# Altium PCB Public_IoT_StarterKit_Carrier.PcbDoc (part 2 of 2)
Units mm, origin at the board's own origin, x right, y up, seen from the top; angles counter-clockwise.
Board outline 84.62 x 84.55 mm, 4 copper layers (Top, PWR, MID, Bottom), stack 1.612 mm thick; 85 components, 101 nets, 416 pads, 114 vias.
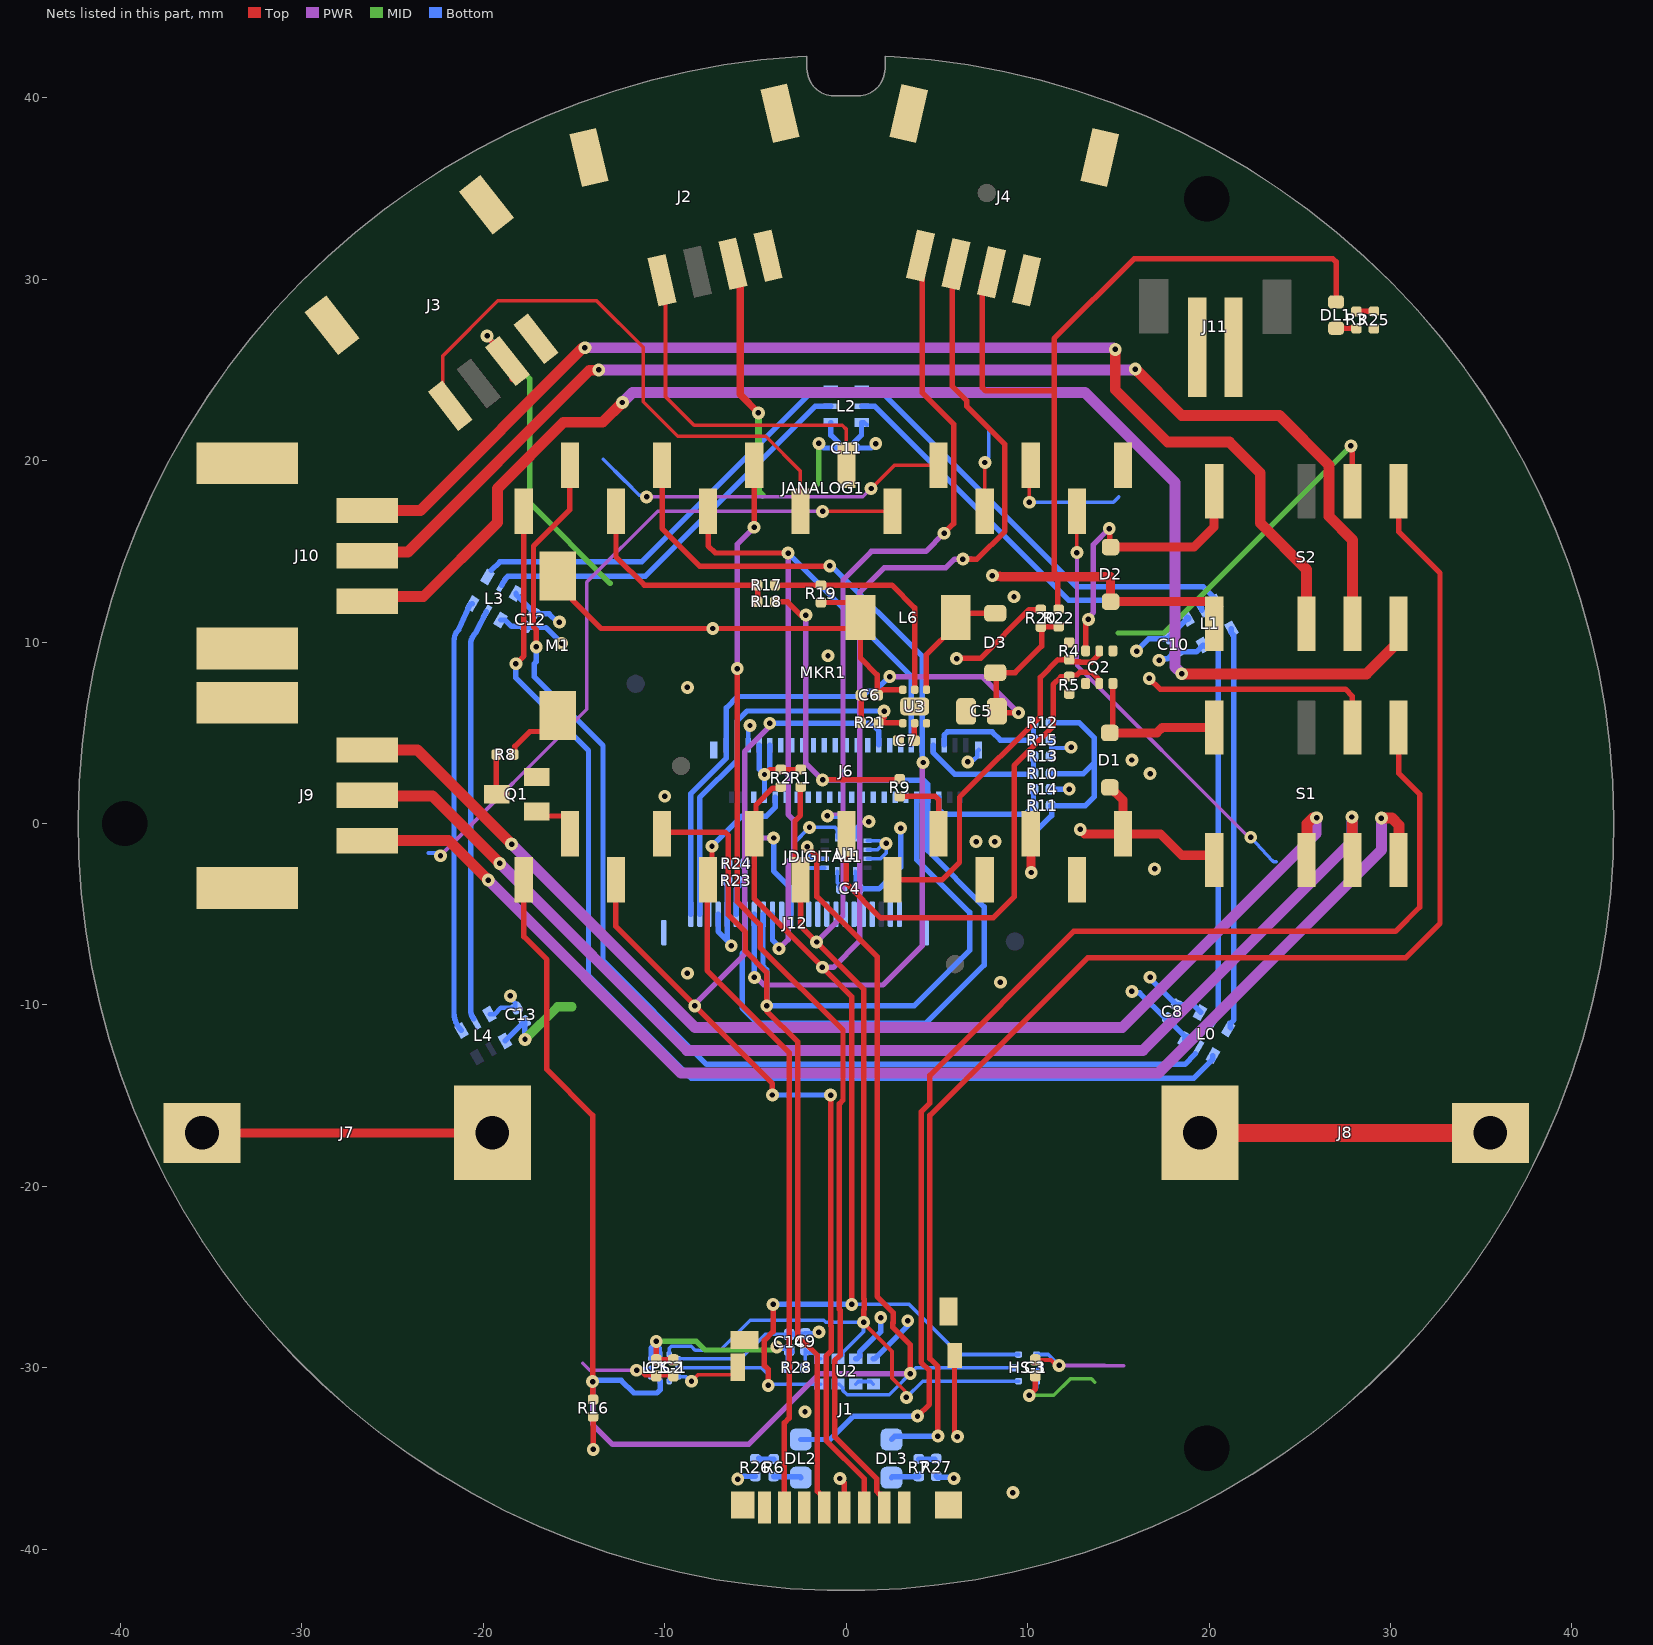
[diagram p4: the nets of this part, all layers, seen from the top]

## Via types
v1: diameter 0.706, hole 0.3, Top to Bottom, tented both sides, 114 vias

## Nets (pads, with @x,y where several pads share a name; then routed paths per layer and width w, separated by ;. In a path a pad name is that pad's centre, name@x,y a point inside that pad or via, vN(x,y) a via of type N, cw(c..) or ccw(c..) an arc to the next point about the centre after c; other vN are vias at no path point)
+5V: C8.2 C10.2 C11.2 C12.2 C13.2 D1.C D2.C DL1.A J2.3 J3.3 J4.3 JDIGITAL1.14 L0.3 L1.3 L2.3 L3.3 L4.3 MKR1.5V R22.1 S1.1 S1.9 S2.1 S2.9 | length 157.9
  Top w0.3: v1(-19.79,26.87) -19.79,26.813 -18.67,25.693 J3.3@-18.67,25.487 -18.39,25.207 J3.3@-18.39,24.475 ; J4.3@8.003,30.382 7.51,29.89 7.51,24.019 7.686,23.844 11.466,23.844 ; 8.462,13.747 8.462,13.664 8.501,13.624 8.526,13.6 ; 11.398,13.6 11.466,13.668 11.466,23.844 ; 11.66,13.6 11.66,11.922 11.745,11.837 11.752,11.837 11.752,11.822 11.727,11.797 R22.1@11.712,11.797 ; v1(16.7,8) 17.298,7.402 27.51,7.402 27.904,7.008 S1.9@27.904,5.29 ; DL1.A@27,28.743 27,30.948 26.824,31.123 15.868,31.123 11.466,26.721 11.466,23.844 ; v1(27.816,20.812) 27.904,20.724 S2.9@27.904,18.315
  Top w0.4: J2.3@-6.246,30.846 -5.842,30.442 -5.842,23.638 v1(-4.834,22.63)
  Top w0.5: v1(8.063,13.664) 8.102,13.624 8.501,13.624 ; 8.526,13.6 11.398,13.6 11.66,13.6 14.576,13.6 D2.C@14.576,12.225 20.034,12.225 S2.1@20.284,11.975 ; v1(12.9,-0.326) 13.143,-0.569 MKR1.5V@15.256,-0.569 ; D1.C@14.534,1.985 14.564,1.985 15.25,1.299 15.25,-0.563 MKR1.5V@15.256,-0.569 ; S1.1@20.284,-2.01 20.284,-2 20.034,-1.75 18.5,-1.75 17.319,-0.569 MKR1.5V@15.256,-0.569
  MID w0.3: v1(-19.79,26.87) -17.439,24.52 -17.439,17.678 -13.001,13.24 ; -1.721,18.583 -1.499,18.806 v1@-1.499,20.887 ; 15,10.5 17.504,10.5 v1(27.816,20.812)
  MID w0.4: v1(-4.834,22.63) -4.834,18.298 -4.611,18.075
  MID w0.5: v1(-17.7,-11.9) -15.9,-10.1 -15.1,-10.1 ; v1(16.7,8) v1@16.739,7.961
  Bottom w0.3: L3.3@-19.046,11.214 -18.788,11.214 -18.44,10.865 -17.65,10.865 C12.2@-17.636,10.851 -17.588,10.803 -16.551,10.803 v1(-15.685,9.938) ; L4.3@-18.796,-11.977 -17.759,-10.94 -17.703,-10.94 -17.703,-11.897 v1(-17.7,-11.9) v1@-17.776,-11.976 ; v1(-1.501,20.949) -1.247,20.694 C11.2@-0.438,20.694 ; L2.3@-0.85,22.1 -0.845,22.095 -0.845,21.4 -0.435,20.99 ; v1(16.005,9.505) 16.673,10.173 17.769,10.173 17.769,10.246 L1.3@18.824,11.301 ; v1(16.75,-8.472) 16.75,-8.555 C8.2@18.198,-10.003 18.21,-9.99 19.131,-9.99 L0.3@19.534,-10.393
  Bottom w0.4: L1.3@18.814,11.31 L1.3@18.824,11.301
BUZZER: JDIGITAL1.2 MKR1.7 Q1.1 | length 2.7
  Top w0.3: Q1.1@-17.061,0.659 -16.816,0.415 -15.574,0.415 -15.224,0.065 MKR1.7@-15.224,-0.569
CS: J6.37 J12.17 JANALOG1.11 MKR1.2 | length 50.6
  Top w0.3: MKR1.2@-10.144,19.751 -10.144,16.259 -8.056,14.171 v1@-0.929,14.171 ; v1(4.239,3.361) v1@4.239,3.471
  PWR w0.3: v1(-5.057,-8.483) -4.947,-8.483 -4.53,-8.9 2.028,-8.9 4.2,-6.728 v1@4.2,3.361
  Bottom w0.3: J12.17@-5.06,-5 -5.06,-8.48 v1(-5.057,-8.483) ; v1(-0.9,14.2) -0.8,14.2 4.2,9.2 J6.37@4.2,4.325 4.2,3.4 v1(4.239,3.361)
DB0: J6.28
DB1: J12.11
DB01: J6.27
DB2: J12.10
DB02: J6.26
DB3: J12.9
DB03: J6.25
DB4: J12.8
DB04: J6.24
DB5: J12.7
DB05: J6.23
DB6: J12.6
DB06: J6.22
DB7: J12.5
DB07: J6.21
DB08: J6.20
DB09: J6.19
DB10: J6.18
DB11: J6.17
DB12: J6.16
DB13: J6.15
DB14: J6.14
DB15: J6.13
DB16: J6.12
DB17: J6.11
DE: J6.31
DIN(SDA): J1.3 J6.29 J12.13 JDIGITAL1. MKR1.8 | length 72.8
  Top w0.3: MKR1.8@-12.684,-3.109 -12.7,-3.124 -12.7,-5.66 -8.342,-10.018 v1(-8.342,-10.054) -4.062,-14.333 v1(-4.062,-14.962) ; v1(-0.855,-14.97) -0.855,-27.676 -0.814,-27.718 -0.814,-29.057 -1.108,-29.352 -1.108,-33.991 0.998,-36.097 J1.3@0.998,-37.694
  PWR w0.3: v1(-8.342,-10.054) -8.342,-9.955 -5.6,-7.213 -5.6,-0.863 ; v1(-4.211,5.52) -4.211,5.357 -5.6,3.968 -5.6,-0.863 ; v1(-4,-0.8) -5.537,-0.8 -5.6,-0.863
  Bottom w0.3: v1(-4.211,5.52) 1.367,5.52 1.8,5.087 J6.29@1.8,4.325 ; v1(-4.062,-14.962) -0.863,-14.962 v1(-0.855,-14.97) ; v1(-4,-0.8) -4,-2.607 -3.06,-3.547 J12.13@-3.06,-5
DISP_BL: R17.2 R19.1 U3.5 | length 12.7
  Top w0.3: R17.2@-3.924,13.132 -3.923,13.131 -1.387,13.131 R19.1@-1.386,13.13 -1.384,13.132 2.526,13.132 3.775,11.883 U3.5@3.775,7.373
DISP_DC: J6.35 J12.15 JANALOG1.10 MKR1.1 | length 44.2
  Top w0.3: MKR1.1@-7.604,17.211 -7.604,15.304 -7.207,14.907 -3.507,14.907 -3.5,14.9 v1(-3.2,14.9)
  PWR w0.3: v1(-3.7,-6.9) -3.2,-6.4 -3.2,-2.107 -2.9,-1.807 -2.9,0.2 -3.2,0.5 v1(-3.2,14.9)
  Bottom w0.3: J12.15@-4.06,-5 -4.06,-6.43 -3.7,-6.79 v1(-3.7,-6.9) ; v1(-3.2,14.9) 3.6,8.1 J6.35@3.6,4.325
DISP_RST: J6.38 J12.18 R9.1 R18.2 | length 53.1
  Top w0.3: R18.2@-3.924,12.215 -3.229,12.215 -2.503,11.489 v1(-2.219,11.489) ; v1(-1.3,2.4) 2.9,2.4 R9.1@2.95,2.45
  PWR w0.3: v1(-2.219,11.489) -2.219,3.319 v1(-1.3,2.4)
  Bottom w0.3: J12.18@-5.56,-5 -5.56,-6.998 -5.738,-7.177 -5.738,-10.162 -4.9,-11 4.4,-11 7.6,-7.8 7.6,-4.6 4.5,-1.5 J6.38@4.5,1.45 4.5,2.158 4.267,2.391 -1.291,2.391 v1(-1.3,2.4)
GND: C1.2 C2.1 C3.1 C4.1 C5.1 C6.1 C7.1 C8.1 C9.1 C10.1 C11.1 C12.1 C13.1 C14.2 HS-1.5 J1.6 J1.CD2 J1.SH1 J1.SH2 J1.SH3 J1.SH4 J2.4 J2.SS1 J2.SS2 J3.4 J3.SS1 J3.SS2 J4.4 J4.SS1 J4.SS2 J6.5 J6.6 J6.MP1 J6.MP2 J7.1 J7.2 J7.- J9.MP1 J9.MP2 J10.MP1 J10.MP2 J11.1 J12.1 J12.2 J12.14 J12.22 J12.MP1 J12.MP2 JDIGITAL1.11 L0.4 L1.4 L2.4 L3.4 L4.4 LPS-1.3 LPS-1.5 LPS-1.8 LPS-1.9 MKR1.GND pad.H10 pad.H11 Q1.2 Q2.1 Q2.4 R4.2 R5.2 R13.1 R14.1 R15.1 R21.1 R24.1 R25.1 R26.1 R27.1 U1.1 U1.2 U1.3 U1.6 U1.7 U2.6 U3.3 U3.7 | length 81.3
  Top w0.2: v1(-11.548,-30.127) -11.411,-30.127 -11.104,-30.435 C1.2@-10.465,-30.435 C2.1@-9.519,-30.435 ; v1(-8.524,-30.742) -8.152,-30.37 -6.277,-30.37 -5.977,-30.07 J1.SH4@-5.977,-29.969 ; J1.CD2@-5.977,-28.842 J1.CD2@-5.604,-28.469 ; C3.1@10.425,-29.565 11.293,-29.565 11.597,-29.869 v1(11.734,-29.869)
  Top w0.3: R21.1@0.831,5.55 0.834,5.553 0.834,7.07 C6.1@0.838,7.073 ; J1.SH3@5.973,-29.319 5.973,-33.524 6.131,-33.682 v1(6.131,-33.792) ; MKR1.GND@7.636,-3.109 7.553,-3.025 MKR1.GND@7.7,-2.878
  Top w0.5: J7.1@-35.5,-17.049 J7.-@-19.5,-17.049 J7.2@-18.543,-16.092
  PWR w0.2: -14.51,-29.75 -14.133,-30.127 v1(-11.548,-30.127) ; v1(11.734,-29.869) 14.258,-29.869 14.249,-29.878 15.302,-29.878
  Bottom w0.2: v1(-11.548,-30.127) -11.461,-30.04 -10.785,-30.04 LPS-1.9@-10.745,-30 LPS-1.8@-10.745,-30.5 ; LPS-1.3@-9.255,-29.5 -5.802,-29.5 -4.458,-28.156 -3.22,-28.156 C14.2@-3.162,-28.214 ; LPS-1.5@-9.228,-30.527 LPS-1.5@-9.255,-30.5 -8.821,-30.5 -8.58,-30.742 v1(-8.524,-30.742) ; U1.7@-0.5,-2.625 -0.5,-3.232 -0.235,-3.498 0,-3.263 U1.6@0,-2.625 ; U1.3@1.175,-1.95 1.891,-1.95 2.2,-1.641 v1(2.2,-1.1) ; U1.2@1.175,-1.45 1.726,-1.45 v1@2,-1.176 ; U1.1@1.175,-0.95 1.85,-0.95 v1@2,-1.1 ; HS-1.5@10.49,-29.265 HS-1.5@10.5,-29.265 11.131,-29.265 v1(11.734,-29.869) ; R13.1@11.275,3.695 11.275,4.135 ; R15.1@11.275,4.6 11.275,4.135 ; v1(12.4,4.2) 12.36,4.16 11.3,4.16 11.275,4.135
  Bottom w0.25: L4.4@-19.646,-10.505 -19.374,-10.505 -19.028,-10.159 -18.287,-10.159 -18.226,-10.098 -18.226,-9.897 -18.5,-9.624 v1(-18.5,-9.5) v1@-18.641,-9.5 ; J6.5@-5.4,4.325 -5.4,5.3 v1(-5.3,5.4) ; C4.1@-0.374,-3.461 C4.1@-0.235,-3.6 ; L2.4@0.85,22.1 1,22.1 L2.4@1.125,21.975 ; v1@2,-1.176 v1@2,-1.1 ; v1(6.704,3.394) 6.791,3.481 7.011,3.481 7.225,3.696 7.225,3.975 J6.MP2@7.3,4.05
  Bottom w0.3: L3.4@-18.196,12.686 -18.196,12.62 -17.201,11.625 C12.1@-17.201,11.605 -17.153,11.557 -16.367,11.557 -15.91,11.1 v1(-15.8,11.1) ; v1(-5.977,-36.134) -5.867,-36.134 -5.709,-35.975 R26.1@-5,-35.975 ; C14.2@-3.139,-28.156 -3.126,-28.143 -2.263,-28.143 C9.1@-2.25,-28.13 -2.249,-28.131 -1.6,-28.131 v1(-1.5,-28.032) ; C11.1@0.432,20.694 1.383,20.694 v1(1.626,20.938) ; 0.435,20.99 0.845,21.4 0.845,22.095 L2.4@0.85,22.1 ; U2.6@0.53,-29.5 0.59,-29.5 0.74,-29.35 0.74,-29.136 1.68,-28.196 1.729,-28.196 1.904,-28.02 v1(1.904,-27.233) ; R27.1@4.958,-35.958 5.026,-36.026 5.874,-36.026 v1(5.942,-36.095) ; R14.1@11.275,1.9 v1(12.3,1.9) ; v1(15.75,-9.25) 15.828,-9.328 16.179,-9.328 17.607,-10.756 C8.1@17.763,-10.756 17.763,-10.827 L0.4@18.742,-11.807 ; v1(17.25,9) 17.328,9.078 17.707,9.078 18.096,9.467 C10.1@18.252,9.467 18.264,9.455 19.299,9.455 L1.4@19.674,9.829 L1.4@19.749,9.754 ; L0.4@18.651,-11.897 L0.4@18.742,-11.807 ; L0.4@18.742,-11.807 18.796,-11.753 18.796,-11.86 L0.4@18.742,-11.807
  other v1: 9.193,-36.871 -2.267,-32.421 8.5,-8.75 -8.75,-8.25 17,-2.5 7.159,-1 8.2,-1 -10,1.5 16.75,2.75 15.75,3.5 -8.75,7.5 -1,9.25 9.25,12.5
GROVE_AN5: J2.1 JANALOG1.7 MKR1.A5 | length 19.2
  Top w0.2: J2.1@-10.143,29.946 -9.952,29.755 -9.952,23.521 -8.38,21.949 -0.219,21.949 0.016,21.714 MKR1.A5@0.016,19.751
GROVE_AN6: J3.1 JANALOG1.8 MKR1.A6 | length 31.9
  Top w0.2: J3.1@-21.752,22.918 -22.239,23.405 -22.239,25.767 -19.197,28.808 -13.756,28.808 -11.188,26.24 -11.188,23.25 -9.277,21.339 -4.438,21.339 -2.524,19.425 MKR1.A6@-2.524,17.211
HSYNC: J6.32
IM0: J6.39 R10.1 R13.2 | length 7.4
  Bottom w0.3: J6.39@4.8,4.325 4.8,3.9 5.987,2.713 10.289,2.713 R10.1@10.325,2.749 R13.2@10.325,3.695
IM1: J6.40 R11.1 R14.2 | length 7.1
  Bottom w0.3: J6.40@5.1,1.45 5.1,0.8 5.4,0.5 9.852,0.5 10.185,0.833 10.2,0.833 10.325,0.958 R11.1@10.325,0.973 R14.2@10.325,1.9
IM2: J6.41 R12.1 R15.2 | length 6.7
  Bottom w0.3: J6.41@5.4,4.325 5.4,4.877 5.576,5.053 8.043,5.053 8.496,4.6 R15.2@10.325,4.6 R12.1@10.325,5.547
INT: HS-1.3 JDIGITAL1.1 LPS-1.7 MKR1.6 R16.1 U1.9 U2.2 | length 100.3
  Top w0.3: MKR1.6@-17.764,-3.109 -17.764,-6.236 -16.5,-7.5 -16.5,-13.552 -13.973,-16.079 v1(-13.973,-30.758) ; v1@-13.961,-30.719 -13.961,-31.731 R16.1@-13.949,-31.743 ; v1(-2.139,-1.293) -2.126,-1.293 -1.609,-1.81 -1.609,-4.031 1.702,-7.342 1.702,-26.068 2.585,-26.951 2.585,-27.516 2.575,-27.526 2.575,-27.775 3.535,-28.735 v1(3.535,-30.316)
  PWR w0.3: v1(-13.973,-30.758) -13.973,-33.113 -12.874,-34.212 -12.281,-34.212 -12.274,-34.205 -5.357,-34.205 -1.468,-30.316 v1(3.535,-30.316)
  Bottom w0.2: v1(-2.139,-1.293) -2.042,-1.39 -2.042,-1.809 -1.902,-1.95 U1.9@-1.175,-1.95 ; U2.2@-0.44,-30.9 -0.38,-30.9 -0.18,-31.1 -0.18,-31.243 0.055,-31.478 2.373,-31.478 3.851,-30 HS-1.3@9.265,-30
  Bottom w0.3: v1(-13.973,-30.758) -13.904,-30.69 -12.399,-30.69 -11.704,-31.386 -10.426,-31.386 -10.25,-31.21 LPS-1.7@-10.25,-30.745
LEDA: C5.2 D3.C J6.1 J12.24 R20.1 R22.2 | length 39
  Top w0.3: C5.2@7.998,6.1 C5.2@8.23,6.1 ; C5.2@8.122,5.992 C5.2@8.23,6.1 ; v1(9.5,6.1) C5.2@8.23,6.1 ; R22.2@11.712,10.847 11.706,10.841 10.736,10.841 R20.1@10.73,10.834 10.768,10.796 10.768,9.779 9.308,8.32 D3.C@8.219,8.32 8.263,8.275 8.263,6.222 C5.2@8.308,6.178 C5.2@8.23,6.1
  PWR w0.3: v1(2.4,8.1) 7.5,8.1 v1(9.5,6.1)
  Bottom w0.3: J12.24@-8.56,-5 -8.56,1.64 -6.6,3.6 J6.1@-6.6,4.325 -6.6,6.375 -5.975,7 0.9,7 1.2,7.3 1.6,7.3 v1(2.4,8.1)
LEDCKI: JANALOG1.13 L0.5 MKR1.4 | length 65.1
  Top w0.3: v1(-17.083,9.735) -17.083,10.683 -17.23,10.83 -17.23,15.292 -15.224,17.298 MKR1.4@-15.224,19.751
  Bottom w0.3: v1(-17.083,9.735) -17.083,8.921 -17.2,8.804 -17.2,8.1 -13.4,4.3 -13.4,-7.556 -7.687,-13.269 18.662,-13.269 L0.5@19.235,-12.696
LEDK: J6.3 J12.23 R21.2 U3.1 | length 22
  Top w0.3: v1(2.094,6.196) 2.094,5.863 R21.2@1.781,5.55 3.098,5.55 U3.1@3.125,5.523
  Bottom w0.3: J12.23@-8.06,-5 -8.073,-4.987 -8.073,1.427 -6,3.5 J6.3@-6,4.325 -6,5.663 -5.462,6.201 2.089,6.201 v1(2.094,6.196)
LEDSDI: JANALOG1.14 L0.6 MKR1.5 | length 64.8
  Top w0.3: v1(-18.2,8.8) -17.764,9.236 MKR1.5@-17.764,17.211
  Bottom w0.3: v1(-18.2,8.8) -18.2,8.022 -14.2,4.022 -14.2,-8.385 -8.536,-14.048 19.147,-14.048 20.21,-12.986 L0.6@20.21,-12.797
MISO: J1.7 J6.10 JDIGITAL1.5 MKR1.10 | length 43.5
  Top w0.3: v1(-7.392,-1.249) -7.392,-2.896 -7.662,-3.166 -7.662,-8.101 -3.139,-12.624 -3.139,-32.765 -3.402,-33.028 J1.7@-3.402,-37.694
  Bottom w0.3: v1(-7.392,-1.249) -5.744,0.4 -4.4,0.4 -3.9,0.9 J6.10@-3.9,1.45
NetC7_2: C7.2 U3.2 | length 1
  Top w0.3: C7.2@3.754,4.57 3.765,4.58 3.765,5.512 U3.2@3.775,5.523
NetC9_2: C9.2 R28.1 U2.8 | length 2.1
  Bottom w0.2: R28.1@-2.275,-30 -2.262,-29.988 -2.262,-29.012 C9.2@-2.25,-29 -2.066,-29.184 -1.786,-29.184 -1.47,-29.5 U2.8@-1.41,-29.5
NetD1_A: D1.A Q2.6 S1.12 | length 8.7
  Top w0.3: D1.A@14.534,4.995 14.699,5.16 Q2.6@14.699,7.715 ; S1.12@20.25,5.256 S1.12@20.284,5.29
  Top w0.5: D1.A@14.534,4.995 17.124,4.995 17.419,5.29 S1.12@20.284,5.29
NetD2_A: D2.A Q2.3 S2.12 | length 16.5
  Top w0.3: Q2.3@13.211,9.527 Q2.3@13.199,9.515 13.199,11.199 13.25,11.25 v1(13.355,11.25) ; v1(14.5,16.25) 14.538,16.212 14.538,15.273 D2.A@14.576,15.235
  Top w0.5: D2.A@14.576,15.235 19.167,15.235 20.266,16.334 20.266,18.296 S2.12@20.284,18.315
  PWR w0.3: v1(13.355,11.25) 13.355,11.358 13.626,11.629 13.626,15.376 v1(14.5,16.25)
NetD3_A: D3.A L6.2 U3.4 | length 6.8
  Top w0.3: U3.4@4.425,7.373 4.425,9.31 6.041,10.926 6.041,11.139 6.492,11.59 D3.A@8.219,11.59
NetDL1_C: DL1.C R3.2 | length 1.1
  Top w0.3: DL1.C@27,27.293 27.009,27.284 27.01,27.285 28.111,27.285 R3.2@28.118,27.278
NetDL2_A: DL2.A S1.8 | length 67.6
  Top w0.3: v1(3.931,-32.658) 4.581,-32.009 4.581,-30.135 4.138,-29.692 4.138,-15.887 4.615,-15.409 4.615,-13.877 12.543,-5.95 30.269,-5.95 31.603,-4.615 31.603,1.622 30.444,2.78 S1.8@30.444,5.29
  Bottom w0.3: DL2.A@-2.5,-33.95 -0.879,-33.95 0.413,-32.658 v1(3.931,-32.658)
NetDL2_C: DL2.C R6.2 | length 1.5
  Bottom w0.3: R6.2@-4,-35.975 -3.962,-36.013 -2.538,-36.013 DL2.C@-2.5,-36.05
NetDL3_A: DL3.A S2.8 | length 77.8
  Top w0.3: v1(5.058,-33.762) 5.058,-29.937 4.615,-29.494 4.615,-16.085 13.3,-7.4 30.829,-7.4 32.727,-5.502 32.727,13.806 30.444,16.089 S2.8@30.444,18.315
  Bottom w0.3: DL3.A@2.5,-33.95 2.687,-33.763 5.057,-33.763 v1(5.058,-33.762)
NetDL3_C: DL3.C R7.2 | length 1.5
  Bottom w0.3: DL3.C@2.5,-36.05 2.538,-36.013 3.962,-36.013 R7.2@4,-35.975
NetJ1_1: J1.1
NetJ1_8: J1.8
NetJ1_CD1: J1.CD1
NetJ9_1: J9.1 S1.3 | length 66.6
  Top w0.6: J9.1@-26.4,4.05 -23.621,4.05 v1(-18.435,-1.135) ; S1.3@25.364,-2.01 25.4,-1.974 25.4,-0.012 25.731,0.319 v1(25.93,0.319)
  PWR w0.6: v1(-18.435,-1.135) -8.321,-11.25 15.215,-11.25 25.909,-0.555 25.909,0.299 v1(25.93,0.319)
NetJ9_2: J9.2 S1.4 | length 68.6
  Top w0.6: J9.2@-26.4,1.55 -26.364,1.514 -22.798,1.514 v1(-19.086,-2.198) ; v1(27.876,0.358) 27.89,0.344 27.89,-1.996 S1.4@27.904,-2.01
  PWR w0.6: v1(-19.086,-2.198) -8.784,-12.5 16.351,-12.5 27.876,-0.974 v1(27.876,0.358)
NetJ9_3: J9.3 S1.5 | length 71.1
  Top w0.6: J9.3@-26.4,-0.95 -26.391,-0.941 -21.904,-0.941 v1(-19.728,-3.118) ; v1(29.498,0.295) 30.076,0.295 30.469,-0.098 30.469,-1.985 S1.5@30.444,-2.01
  PWR w0.6: v1(-19.728,-3.118) -9.096,-13.75 17.206,-13.75 29.498,-1.458 v1(29.498,0.295)
NetJ10_1: J10.1 S2.3 | length 66.5
  Top w0.6: J10.1@-26.4,17.25 -26.393,17.257 -23.467,17.257 -14.524,26.2 -14.418,26.2 v1(-14.398,26.221) ; v1(14.832,26.126) 14.832,23.907 17.724,21.015 21.124,21.015 22.819,19.32 22.819,16.552 25.364,14.007 S2.3@25.364,11.015
  PWR w0.6: v1(-14.398,26.221) 14.737,26.221 v1(14.832,26.126)
NetJ10_2: J10.2 S2.4 | length 68.7
  Top w0.6: J10.2@-26.4,14.75 -26.181,14.969 -24.151,14.969 -14.14,24.98 -13.656,24.98 v1(-13.636,25) ; v1(15.938,25.042) 18.498,22.482 23.873,22.482 26.61,19.745 26.61,16.933 27.91,15.633 27.91,11.021 S2.4@27.904,11.015
  PWR w0.6: v1(-13.636,25) 15.895,25 v1(15.938,25.042)
NetJ10_3: J10.3 S2.5 | length 76.8
  Top w0.6: J10.3@-26.425,12.5 -23.308,12.5 -19.224,16.584 -19.224,18.463 -15.574,22.113 -13.422,22.113 v1(-12.334,23.201) ; v1(18.5,8.25) 28.679,8.25 30.444,10.015 S2.5@30.444,11.015
  PWR w0.6: v1(-12.334,23.201) -11.775,23.761 13.166,23.761 14.875,22.052 18.127,18.8 18.127,8.623 v1(18.5,8.25)
NetJ12_19: J12.19 R23.1 R24.2 | length 3
  Bottom w0.3: J12.19@-6.06,-5 -6.06,-3.622 -5.597,-3.159 R23.1@-5.597,-3.144 -5.587,-3.134 -5.587,-2.222 R24.2@-5.577,-2.212
NetL0_2: L0.2 L1.5 | length 20.8
  Bottom w0.3: L1.5@20.453,10.279 20.499,10.233 20.499,-10.538
NetL1_2: L1.2 L2.5 | length 23.5
  Bottom w0.3: L2.5@0.85,23 1.573,23 12.273,12.3 19.179,12.3 19.603,11.876 L1.2@19.603,11.751
NetL2_2: L2.2 L3.5 | length 22.3
  Bottom w0.3: L3.5@-18.975,13.136 -18.774,13.483 -18.755,13.516 -18.639,13.632 -11.068,13.632 -4.803,19.897 -1.7,23 L2.2@-0.85,23
NetL3_2: L3.2 L4.5 | length 22.7
  Bottom w0.3: L4.5@-20.514,-10.755 cw(c-20.064,-10.306) -20.7,-10.306 -20.7,9.836 cw(c-19.761,9.836) -20.425,10.5 L3.2@-19.825,11.664
NetM1_2: M1.2 R8.2 | length 4
  Top w0.3: R8.2@-18.325,3.8 -18.253,3.872 -18.253,4.247 -17.429,5.071 -16.752,5.071 -15.902,5.921 M1.2@-15.902,5.95 ; M1.2@-16.19,5.075 M1.2@-15.902,5.363
NetQ1_3: Q1.3 R8.1 | length 2.4
  Top w0.3: Q1.3@-19.461,1.609 Q1.3@-19.261,1.609 -19.275,1.623 R8.1@-19.275,3.8
NetR3_1: R3.1 R25.2 | length 1
  Top w0.3: R3.1@28.118,28.228 28.12,28.226 29.081,28.226 R25.2@29.084,28.223
NetR6_1: R6.1 R26.2 | length 0.8
  Bottom w0.3: R26.2@-4.825,-34.97 -4.767,-34.97 -4.712,-35.025 R6.1@-4,-35.025
NetR7_1: R7.1 R27.2 | length 0.9
  Bottom w0.3: R7.1@4,-35.025 R27.2@4.88,-35.025
NetU2_3: U2.3 U2.4 | length 1.1
  Bottom w0.2: U2.3@0.53,-30.9 0.68,-30.75 1.35,-30.75 U2.4@1.5,-30.9
PA02_AIN0: JANALOG1.2 MKR1.A0 | length 24.1
  Top w0.2: MKR1.A0@12.716,17.374 MKR1.A0@12.716,17.211 12.716,14.934 v1(12.72,14.93)
  PWR w0.2: v1(12.72,14.93) 12.724,14.926 12.724,8.709 22.136,-0.703 ccw(c22.276,-0.561) 22.27,-0.761 v1(22.294,-0.762)
  Bottom w0.2: v1(22.294,-0.762) 23.479,-2.046 ccw(c23.626,-1.91) 23.626,-2.11 23.687,-2.11
PA03_VREFA: JANALOG1.1 MKR1.AREF
PA04_AIN4: JANALOG1.5 MKR1.A3 | length 20.1
  Top w0.2: v1(1.376,18.462) 2.666,19.751 MKR1.A3@5.096,19.751
  PWR w0.2: v1(-11,18.001) 0.916,18.001 v1(1.376,18.462)
  Bottom w0.2: -13.384,20.077 -12.155,18.848 -12.148,18.848 -11.398,18.098 -11.097,18.098 v1(-11,18.001)
PA05_AIN5: JANALOG1.6 MKR1.A4 | length 37.6
  Top w0.2: v1(-1.3,17.2) 2.544,17.2 MKR1.A4@2.556,17.211
  PWR w0.2: v1(-22.356,-1.772) -22.356,-1.765 -14.3,6.291 -14.3,9.34 -14.294,9.346 -14.294,13.306 -10.389,17.211 -1.311,17.211 v1(-1.3,17.2)
  Bottom w0.2: -23.021,-1.625 -22.495,-1.625 -22.356,-1.765 v1(-22.356,-1.772)
PA08_S0_I2C_SDA: HS-1.4 J4.2 JDIGITAL1.6 LPS-1.4 MKR1.11 R2.1 U1.14 U2.1 | length 109.3
  Top w0.3: v1(-4.29,-30.968) -4.29,-30.087 -4.501,-29.876 -4.501,-29.105 -4.501,-28.482 -4.023,-28.004 v1(-4.023,-26.5) ; R2.1@-3.6,2.025 -3.672,1.953 -4.047,1.953 -4.97,1.03 -4.97,-0.474 MKR1.11@-5.064,-0.569 -5.064,-4.154 -1.311,-7.907 v1(-1.311,-7.925) 0.307,-9.543 v1(0.307,-26.5) ; J4.2@6.054,30.832 5.859,30.637 5.859,24.088 6.643,23.304 6.643,22.998 8.744,20.896 8.744,16.106 7.21,14.572 v1(6.433,14.572)
  PWR w0.2: 0.738,0.044 1.191,0.044 v1(1.252,0.104)
  PWR w0.3: v1(-1.311,-7.925) -0.704,-7.925 0.738,-6.484 0.738,0.044 0.738,12.73 2.107,14.1 5.5,14.1 5.972,14.572 v1(6.433,14.572) 6.895,14.572
  Bottom w0.2: LPS-1.4@-9.255,-30 -4.678,-30 -4.292,-30.386 -4.292,-30.966 v1(-4.29,-30.968) -4.222,-30.9 U2.1@-1.41,-30.9 ; v1(0.307,-26.5) 3.464,-26.5 6.229,-29.265 HS-1.4@9.5,-29.265 ; U1.14@0.5,-0.775 0.533,-0.742 0.533,-0.251 0.888,0.104 v1(1.252,0.104)
  Bottom w0.3: v1(-4.023,-26.5) v1(0.307,-26.5)
PA09_S0_I2C_SCL: HS-1.2 J4.1 JDIGITAL1.7 LPS-1.2 MKR1.12 R1.1 U1.13 U2.7 | length 103.5
  Top w0.2: v1(0.96,-27.483) 0.96,-27.529 2.526,-29.095 2.526,-30.56 3.227,-31.262 3.227,-31.529 v1(3.324,-31.626)
  Top w0.3: MKR1.12@-2.82,-3.109 -2.82,0.149 -2.524,0.445 R1.1@-2.524,1.8 ; MKR1.12@-2.524,-3.109 -2.5,-3.133 -2.5,-5.663 v1(-1.632,-6.531) 0.96,-9.123 0.96,-26.19 0.988,-26.218 0.988,-26.782 0.96,-26.81 v1(0.96,-27.483) ; J4.1@4.105,31.282 4.189,31.198 4.189,23.752 5.924,22.017 5.924,16.524 v1(5.4,16)
  PWR w0.2: v1(-1.032,0.421) -0.949,0.504 -0.174,0.504
  PWR w0.3: v1(-1.632,-6.531) -0.174,-5.074 -0.174,0.504 -0.174,13.433 1.393,15 4.4,15 v1(5.4,16)
  Bottom w0.2: LPS-1.2@-9.75,-29.255 -9.75,-28.934 -9.633,-28.817 -8.537,-28.817 -8.324,-29.03 -6.94,-29.03 -5.279,-27.369 -1.233,-27.369 -1.119,-27.483 v1(0.96,-27.483) 0.96,-28.017 -0.18,-29.157 -0.18,-29.3 -0.38,-29.5 U2.7@-0.44,-29.5 ; v1(-1.032,0.421) -0.955,0.344 -0.174,0.344 0,0.17 U1.13@0,-0.775 ; v1(3.324,-31.626) 4.215,-30.735 HS-1.2@9.5,-30.735
PA11_TCC0-W3: JANALOG1.12 MKR1.3 R17.1 R18.1 | length 11.9
  Top w0.3: MKR1.3@-12.684,17.211 -12.684,14.7 -11.116,13.132 R17.1@-4.874,13.132 R18.1@-4.874,12.215
PA17_S1_SCK: J1.5 J6.36 J12.16 JDIGITAL1.4 MKR1.9 | length 70.9
  Top w0.3: MKR1.9@-10.144,-1.181 MKR1.9@-10.144,-0.569 -10.046,-0.47 -6.676,-0.47 -6.5,-0.646 -6.5,-5.028 -5.56,-5.968 -5.56,-7.017 -4.376,-8.201 -4.376,-10.04 v1(-4.378,-10.042) -4.378,-10.32 -2.662,-12.036 -2.662,-28.293 -2.242,-28.713 -2.179,-28.713 -1.586,-29.305 -1.586,-36.793 -1.41,-36.969 -1.402,-36.969 -1.202,-37.169 J1.5@-1.202,-37.694
  Bottom w0.3: J12.16@-4.56,-5 -4.56,-5.594 -4.582,-5.616 -4.582,-7.855 -4.376,-8.061 -4.376,-10.04 v1(-4.378,-10.042) 3.758,-10.042 6.8,-7 6.8,-4.9 3.9,-2 J6.36@3.9,1.45
PA22_TC4-W0: J1.2 JANALOG1.9 MKR1.0 | length 61.6
  Top w0.3: v1(-6,8.538) -6,-4.322 -4.737,-5.585 -4.737,-6.826 -0.174,-11.389 -0.174,-15.252 -0.374,-15.452 -0.374,-26.782 -0.336,-26.821 -0.336,-29.313 -0.63,-29.608 -0.63,-33.793 1.676,-36.099 1.676,-36.793 1.851,-36.969 1.898,-36.969 2.098,-37.169 J1.2@2.098,-37.694 ; v1(-5.073,16.327) -5.064,16.336 MKR1.0@-5.064,19.751
  PWR w0.3: v1(-6,8.538) -6,15.4 v1(-5.073,16.327)
PB02_AIN10: JANALOG1.3 MKR1.A1 | length 7.1
  Top w0.2: v1(10.1,17.7) 10.1,19.676 MKR1.A1@10.176,19.751
  Bottom w0.2: v1(10.1,17.7) 14.729,17.7 15.027,17.998
PB03_AIN11: JANALOG1.4 MKR1.A2 | length 4.6
  Top w0.2: MKR1.A2@7.636,17.211 7.645,17.221 v1(7.645,19.896)
  Bottom w0.2: v1(7.645,19.896) 7.7,19.95 7.7,20 7.866,20.166 7.866,21.707
PB22_S5_TX: JDIGITAL1.9 MKR1.14 Q2.2 R4.1 | length 20.2
  Top w0.3: MKR1.14@2.556,-3.109 5.277,-3.109 6.247,-2.138 6.247,1.447 10.7,5.9 10.7,8.051 11.68,9.031 R4.1@12.298,9.031 12.423,8.906 12.868,8.906 12.887,8.887 13.512,8.887 13.899,9.275 13.899,9.465 Q2.2@13.949,9.515
PB23_S5_RX: JDIGITAL1.8 MKR1.13 Q2.5 R5.1 | length 28.3
  Top w0.3: MKR1.13@0.016,-1.319 0.016,-3.312 1.904,-5.2 8.1,-5.2 9.253,-4.047 9.253,3.19 11.409,5.347 11.409,7.662 11.834,8.087 12.292,8.087 12.388,8.183 12.727,8.183 12.887,8.343 13.512,8.343 13.899,7.955 13.899,7.765 Q2.5@13.949,7.715
PCLK: J6.30
RD: J6.34
RESET#: JDIGITAL1.10 MKR1.RST R9.2 | length 4.1
  Top w0.3: R9.2@2.95,1.5 4.92,1.5 5.096,1.324 MKR1.RST@5.096,-0.569
SDO0: L0.1 L1.6 | length 22.1
  Bottom w0.3: L0.1@21.202,-11.263 21.18,-11.241 21.18,-11.019 21.371,-10.828 21.371,10.373 21.232,10.512 L1.6@21.232,10.729
SDO1: L1.1 L2.6 | length 24.4
  Bottom w0.3: L2.6@0.85,23.9 1.842,23.9 12.707,13.036 19.692,13.036 20.28,12.447 cw(c20.034,12.201) L1.1@20.382,12.201
SDO2: L2.1 L3.6 | length 22.8
  Bottom w0.3: -19.567,13.945 -19.086,14.425 -11.275,14.425 -1.8,23.9 L2.1@-0.85,23.9
SDO3: L3.1 L4.6 | length 23.9
  Bottom w0.3: -21.613,10.081 -21.613,-10.418 ccw(c-20.218,-10.418) L4.6@-21.204,-11.405 ; -21.613,10.082 cw(c-20.795,10.082) -21.549,10.398 cw(c-20.741,10.062) -21.39,10.65 cw(c-20.741,10.062) -21.36,10.681 -20.72,12.071 L3.1@-20.604,12.114
TE: J12.4
VBAT: J8.1 J8.2 J8.- J11.2 pad.H8 pad.H9 | length 16.8
  Top w0.6: J8.1@35.5,-17.049 J8.1@36.05,-16.499
  Top w1: J8.-@19.5,-17.049 J8.1@35.5,-17.049
VCC: C1.1 C2.2 C3.2 C4.2 C6.2 C14.1 HS-1.1 HS-1.6 J1.4 J6.7 J6.8 J6.9 J12.20 J12.21 JDIGITAL1.12 L6.1 LPS-1.1 LPS-1.6 LPS-1.10 M1.1 MKR1.VCC R1.2 R2.2 R10.2 R11.2 R12.2 R16.2 R19.2 R20.2 R23.2 R28.2 U1.5 U1.8 U1.12 U2.5 U3.6 | length 103.1
  Top w0.3: M1.1@-15.902,13.65 -15.097,12.845 -15.097,12.347 -13.498,10.748 v1(-7.347,10.748) 0.569,10.748 L6.1@0.791,10.97 ; R16.2@-13.949,-32.693 -13.942,-32.699 -13.942,-34.484 v1(-13.935,-34.491) ; v1(-10.468,-28.542) -10.468,-29.561 C1.1@-10.465,-29.565 C2.2@-9.519,-29.565 ; v1(-4.5,2.7) -4.225,2.975 R2.2@-3.6,2.975 R1.2@-2.5,2.975 ; R19.2@-1.386,12.18 0.116,12.18 0.791,11.505 L6.1@0.791,11.351 L6.1@0.791,10.97 ; v1(-0.346,-36.097) -0.102,-36.34 J1.4@-0.102,-37.694 ; U3.6@3.125,7.373 2.033,7.373 1.733,7.073 C6.2@1.708,7.073 1.708,8.192 0.791,9.108 L6.1@0.791,10.97 ; v1(6.09,9.09) 6.103,9.103 7.408,9.103 10.09,11.784 R20.2@10.73,11.784 ; v1(10.088,-31.515) 10.425,-31.177 C3.2@10.425,-30.435
  Top w0.5: MKR1.VCC@10.176,-0.569 10.188,-0.581 10.188,-2.688 v1(10.2,-2.7)
  MID w0.2: v1(10.088,-31.515) 11.444,-31.515 12.362,-30.597 13.518,-30.597 13.707,-30.786
  MID w0.3: v1(-10.468,-28.542) -8.249,-28.542 -7.774,-29.016 -4.102,-29.016 -3.93,-28.845 v1(-3.82,-28.845)
  Bottom w0.2: v1@-10.468,-28.628 -10.468,-28.675 -10.25,-28.893 LPS-1.1@-10.25,-29.255 -10.25,-29.77 -9.75,-30.27 LPS-1.6@-9.75,-30.745 ; U1.8@-1.175,-2.45 -2.433,-2.45 -2.7,-2.183 -2.7,-1.795 -2.878,-1.617 -2.878,-1.072 v1(-2.019,-0.213) -0.615,-0.213 -0.5,-0.328 U1.12@-0.5,-0.775 ; C4.2@0.5,-3.365 U1.5@0.5,-2.625 ; v1(10.088,-31.515) 10.5,-31.102 10.5,-30.117 ; HS-1.1@10.5,-30.735 10.5,-30.117 ; HS-1.6@10.735,-30 10.617,-30 10.5,-30.117
  Bottom w0.3: LPS-1.10@-10.745,-29.5 -10.745,-28.906 v1@-10.468,-28.628 ; J12.21@-7.06,-5 -7.06,-5.94 v1@-6.335,-6.665 ; R23.2@-6.547,-3.144 -6.547,-4.437 -6.56,-4.45 J12.20@-6.56,-5 -6.56,-6.406 -6.335,-6.631 v1@-6.335,-6.665 ; v1(-6.335,-6.741) v1@-6.335,-6.665 ; J6.7@-4.8,4.325 -4.8,3 v1(-4.5,2.7) ; J6.8@-4.5,1.45 v1(-4.5,2.7) ; J6.9@-4.2,4.325 -4.2,3 v1(-4.5,2.7) ; v1(-3.82,-28.845) -3.743,-28.923 -3.192,-28.923 C14.1@-3.008,-29.107 ; R28.2@-3.225,-30 -3.182,-29.957 -3.182,-29.069 C14.1@-3.139,-29.026 ; C4.2@0.5,-3.365 C4.2@0.635,-3.5 ; C4.2@0.635,-3.6 1.8,-3.6 3,-2.4 v1(3,-0.253) ; U2.5@1.5,-29.5 1.56,-29.5 v1@3.435,-27.625 ; v1(10.2,-2.7) 10.2,-0.7 11.33,0.43 11.33,0.918 R11.2@11.275,0.973 13.173,0.973 13.678,1.478 13.678,3.352 ; R10.2@11.275,2.749 13.075,2.749 13.678,3.352 ; R12.2@11.275,5.547 12.853,5.547 13.678,4.722 13.678,3.352
  other v1: 3.4,-27.4
VIN: JDIGITAL1.13 MKR1.VIN
VSYNC: J6.33
pads on no net: FD1.1 FD2.1 FD3.1 FD4.1 FD5.1 FD6.1 J2.2 J3.2 J6.2 J6.4 J6.42 J6.43 J6.44 J6.45 J11.MP1 J11.MP2 J12.3 J12.12 L4.1 L4.2 S1.10 S2.10 U1.4 U1.10 U1.11

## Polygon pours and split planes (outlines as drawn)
PA04_AIN4 on Bottom "poligonTest" (solid, pour order 66): -12.483,19.318 -22.369,36.489 ccw(c-0.195,0.118) -42.712,2.737 -22.925,1.86 cw(c0,0)
PB02_AIN10 on Bottom "poligonTest" (solid, pour order 57): 22.971,1.152 42.784,1.152 ccw(c0.212,0.117) 23.718,35.627 13.073,18.923 cw(c0,0)
PA02_AIN0 on Bottom "poligonTest" (solid, pour order 69): 11.438,-19.954 21.397,-37.067 ccw(c0.299,-0.186) 42.709,-2.793 22.925,-1.86 cw(c0,0)
PB03_AIN11 on Bottom "poligonTest" (solid, pour order 65): 10.488,20.469 20.346,37.655 ccw(c0.006,0.319) -18.981,38.361 -9.852,20.783 cw(c0,0)
PA05_AIN5 on Bottom "poligonTest" (solid, pour order 67): -22.971,-1.152 -42.785,-1.152 ccw(c-0.182,-0.104) -22.75,-36.253 -12.109,-19.554 cw(c0,0)
GND on Bottom "poligonTest" (hatched 90Degree grid 0.508 track 0.203, remove dead copper, pour order 81): -0.145,-16.414 cw(c-0.145,-0.342) -16.217,-0.342 cw(c-0.145,-0.342) -0.145,15.729 cw(c-0.145,-0.342) 15.927,-0.342 cw(c-0.145,-0.342)
VCC on MID "poligonTest" (solid, pour order 75): 10.739,-3.856 1.8,-12.795 1.8,-23.029 2.871,-24.1 12.318,-24.1 14.423,-26.204 14.423,-33.355 10.221,-37.557 -9.08,-37.557 -14.389,-34.733 -14.389,-32.156 -7.154,-24.921 -7.154,0.659 -9.167,2.672 -9.167,10.833 -8.1,11.9 4.256,11.9 10.739,5.417
+5V on MID "poligonTest" (hatched 90Degree grid 0.508 track 0.203, pour order 78): -0.002,-18.989 cw(c-0.002,-0.006) -18.985,-0.006 cw(c-0.002,-0.006) -0.002,18.977 cw(c-0.002,-0.006) 18.981,-0.006 cw(c-0.002,-0.006)
GND on Top "GND_L01_P086" (hatched 90Degree grid 0.508 track 0.25, remove dead copper, pour order 86): -0.425,41.66 ccw(c1.228,-1.108) 2.881,41.66 2.881,40.461 cw(c1.881,40.461) 1.881,39.461 0.575,39.461 cw(c0.575,40.461) -0.425,40.461
VBAT on Top "poligonTest" (solid, pour order 70): 21.019,25.05 21.019,23.462 29.985,23.462 33.618,19.829 33.618,-15.682 35.457,-15.682 35.457,20.55 30.957,25.05
GND on PWR "C" (hatched 90Degree grid 0.508 track 0.203, remove dead copper, pour order 79): -1.653,42.768 ccw(c0,0) 1.653,42.768 1.653,41.569 cw(c0.653,41.569) 0.653,40.569 -0.653,40.569 cw(c-0.653,41.569) -1.653,41.569

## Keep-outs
Bottom:
  circle w5: c20.028,11.015 r0.5
  circle w5: c-20,-11.691 r0.5
  circle w5: c-19.4,12.4 r0.5
  circle w5: c20,-11.691 r0.5
  circle w5: c0,23 r0.5
Keep-Out Layer:
  region: 13.426,-33.631 13.426,-27.355 6.43,-27.355 6.43,-33.631
  region: -6.538,-32.769 -6.538,-27.519 -13.441,-27.519 -13.441,-32.769

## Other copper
Top:
  region net GND: 37.198,-12.179 38.699,-12.358 39.239,-11.947 40.673,-0.679 40.612,0.253 40.219,0.847 38.699,1.131 38.289,0.577 36.554,-11.338
Bottom:
  region net GND: 5.02,-38.48 5.638,-40.163 6.423,-40.541 17.334,-36.906 17.801,-35.953 17.426,-34.888 16.014,-34.201 5.336,-37.818

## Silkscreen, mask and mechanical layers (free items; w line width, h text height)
Top Designator:
  the board outline again, w0.013
Route Tool Path:
  drawing of 494 lines, arcs and shapes, not listed
Board:
  drawing of 666 lines, arcs and shapes, not listed
Bottom Assembly (Mech10):
  circle w0.013: c-39.75,0 r1.25
  circle w0.013: c19.875,-34.425 r1.25
  circle w0.013: c19.875,34.425 r1.25
Top Assembly (Mech13):
  region: 0.665,1.025 1.168,0.361 2.911,2.201
  region: -2.911,-2.201 -0.665,-1.025 -1.168,-0.361
  lines w0.013: 11.983,-1.019 13.817,0.367
Dimensions:
  drawing of 73 lines, arcs and shapes, not listed
Old top silk:
  drawing of 258 lines, arcs and shapes, not listed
